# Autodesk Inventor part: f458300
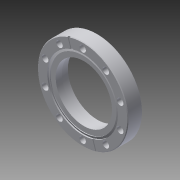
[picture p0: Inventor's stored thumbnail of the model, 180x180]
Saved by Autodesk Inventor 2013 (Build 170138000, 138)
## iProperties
Shininess: 64.0
Length Units: 11272
Angle Units: 11279
Time Units: 11290
Mass Units: 11286
Length Display Precision: 3
Angle Display Precision: 2
Compacted: True
Part Number: f458300
Document SubType Name: Modeling
Created: 2004-11
Designer: ehb9
Manufacturer: Standard
Standards Organization: Custom
Material: Stainless Steel
Mass: 873.626 g
Surface Area: 287.914 cm^2
Volume: 108.122 cm^3
Density: 8.08 g/cm^3
Density: 0.0
Volumn: 0.0
Area: 0.0
PropertySet Name: Model Information
Control State: 0
Master: False
Checked Out: False
Author: ehb9
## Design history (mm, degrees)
sketch "Sketch1"
  geometry: L1 (0, -9.525)-(0, 8.001); L2 (58.674, -9.525)-(0, -9.525); L3 (58.674, 9.525)-(58.674, -9.525); L4 (45.783, 9.525)-(58.674, 9.525); L5 (45.783, 7.919)-(45.783, 9.525); L6 (43.117, 8.89)-(45.783, 7.919); L7 (43.117, 8.001)-(43.117, 8.89); L8 (0, 8.001)-(43.117, 8.001); L9 (0, -9.525)-(0, 8.001)
  constraints: 18 end point, 4 vertical, 3 horizontal, 1 other
  dimensions: "d1" = 0.635 vertical distance of L6.start L4.start; "d3" = 1.524 vertical distance of L7.start L4.start; "d5" = 70 deg angle of L6 L5; "d7" = 43.1165 horizontal distance of L1.end L6.start; "d9" = 45.7835 horizontal distance of L4.start L1.end; "d11" = 58.674 distance of L2.start L1.start; "d13" = 19.05 distance of L3.start L2.start
revolve "RevolutionFull1" sketch "Sketch1" stored, may be unused: angle "d14" = 360 deg
sketch "Sketch2"
  geometry: 1 further point
node "WorkPoint1"
sketch "Sketch3"
  geometry: 1 further point
node "WorkPoint2"
node "Sketch4"
hole "Hole1" sketch "Sketch2" diameter "d18" = 8.4328; stored, may be unused: countersink angle "d22" = 82 deg, drill point angle "d24" = 118 deg; dims "d19" = 12.7, "d20" = 9.525, "d21" = 6.35, "d23" = 19.05
node "Sketch5"
node "Sketch6"
workaxis "Work Axis1"
pattern_circular "PolarArray1" dims angle "d27" = 36 deg
sketch "Sketch7"
  geometry: C1 r 36.513 at (0, 0); C2 r 58.674 at (0, 0) reference
  constraints: 1 centre point, 1 concentric
  dimensions: "d29" = 73.025 diameter of C1
extrude "ExtrusionThru1" cut sketch "Sketch7" stored distance "d30" = 3.302; taper "d31" = 0 deg
sketch "Sketch8"
  geometry: C1 r 38.227 at (0, 0); C2 r 58.674 at (0, 0) reference
  constraints: 1 centre point, 1 concentric
  dimensions: "d33" = 76.454 diameter of C1
extrude "ExtrusionBlind1" cut sketch "Sketch8" distance "d34" = 9.525; taper "d35" = 0 deg
chamfer "Chamfer1" distance "d36" = 0.762; stored, may be unused: second distance "d37" = 3.175, angle "d38" = 45 deg
sketch "Sketch9"
  geometry: L1 (0, 51.181)-(0, 0); L2 (0, 0)-(-24.795, 76.313); L3 (-12.63, 44.007)-(-15.649, 43.026); L4 (-15.649, 43.026)-(-19.642, 55.316); L5 (-19.642, 55.316)-(-16.623, 56.297); L6 (-16.623, 56.297)-(-12.63, 44.007); C1 r 4.216 at (0, 51.181) reference; C2 r 57.912 at (0, 0) reference; A1 r 45.783 centre (0, 0) between (-12.63, 44.007) and (-15.649, 43.026) reference
  constraints: 12 end point, 2 parallel, 2 perpendicular, 2 point on circle, 1 vertical
  dimensions: "d39" = 18 deg angle of L2 L1; "d40" = 1.5875 distance between parallel lines of L2 L4
extrude "Extrusion3" cut sketch "Sketch9" distance "d41" = 1.016; taper "d42" = 0 deg
pattern_circular "Circular Pattern2" dims angle "d45" = 360 deg
body "Solid1"
other parameters: "d0" = 0.635 (derived), "d2" = 1.524 (derived), "d4" = 70 deg (derived), "d6" = 43.1165 (derived), "d8" = 45.7835 (derived), "d10" = 58.674 (derived), "d12" = 19.05 (derived), "d15" = 0, "d16" = 0, "d17" = 0, "d28" = 73.025 (derived), "d32" = 76.454 (derived)
